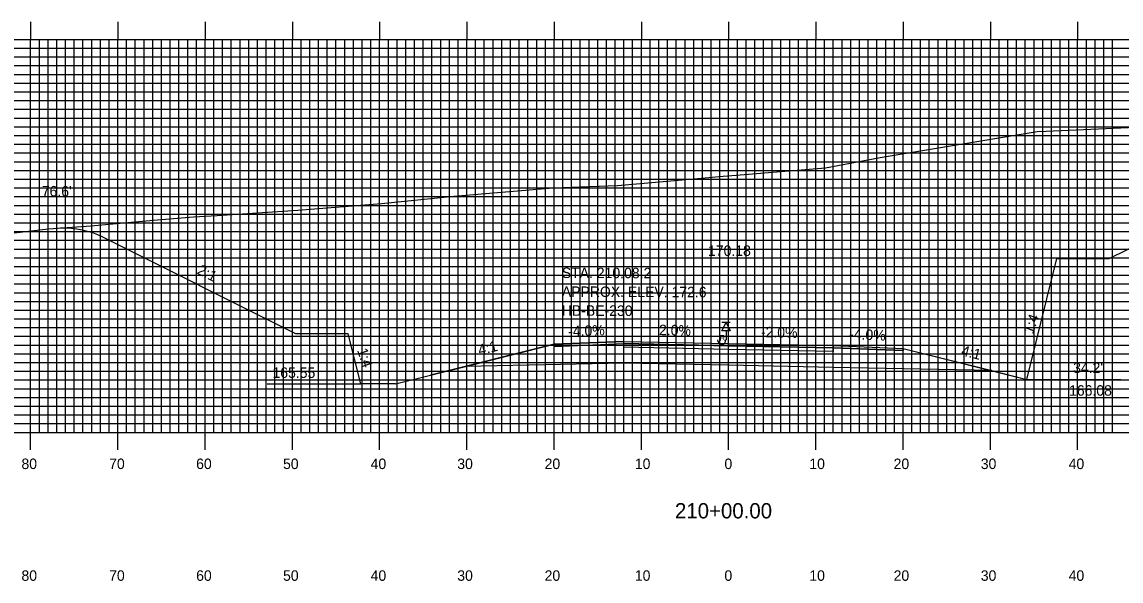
# Model space of a CAD drawing. Extents: x 1794453 to 1794796, y 442591 to 442811.
# Drawn here: x 1794537.4 to 1794663.3, y 442656.6 to 442720.7 of the extents above; entities that cross this region are included whole.
import ezdxf

# ---------------------------------------------------------------- set-up
doc = ezdxf.new("R2010")
doc.units = 0
for name, color, linetype in [('ANNOTATION', 7, 'Continuous'), ('BORING - REFUSAL', 7, 'Continuous'), ('D_Roadway_Centerline', 7, 'Continuous'), ('D_Roadway_Centerline_Text', 7, 'Continuous'), ('D_Roadway_Edge_Shoulder', 7, 'Continuous'), ('D_Roadway_Edge_TW', 7, 'Continuous'), ('D_Roadway_FinishedGrade', 7, 'Continuous'), ('D_Roadway_Pavement', 7, 'Continuous'), ('D_Roadway_SlopeLines', 7, 'Continuous'), ('D_Roadway_SubGrade', 7, 'Continuous'), ('D_Text_Standard', 7, 'Continuous'), ('H_V ANNOTATION', 7, 'Continuous'), ('MAJOR', 7, 'Continuous'), ('MINOR', 7, 'Continuous'), ('PDRAIN', 7, 'Continuous'), ('S_Roadway_Centerline', 7, 'Continuous')]:
    doc.layers.add(name, color=color, linetype=linetype)

msp = doc.modelspace()

# ---------------------------------------------------------------- linework, layer by layer
at = {"layer": 'BORING - REFUSAL'}
for p, q in [((1794618.52, 442686.27), (1794617.56, 442686.27)), ((1794618.04, 442685.31), (1794618.04, 442684.25))]:
    msp.add_line(p, q, dxfattribs=at)
msp.add_lwpolyline([(1794618.04, 442686.27), (1794618.52, 442685.31), (1794617.56, 442685.31)], close=True, dxfattribs=at)
msp.add_arc((1794617.55, 442684.25), 0.485, 180, 0, dxfattribs=at)
at = {"layer": 'D_Roadway_Centerline'}
msp.add_lwpolyline([(1794580.17, 442679.22), (1794588.17, 442681.22), (1794598.34, 442683.77), (1794606.34, 442684.09), (1794618.34, 442683.85), (1794630.34, 442683.61), (1794638.34, 442683.29), (1794648.51, 442680.74), (1794652.51, 442679.74)], dxfattribs=at)
at = {"layer": 'D_Roadway_Edge_Shoulder'}
for points in [[(1794606.34, 442684.09), (1794598.34, 442683.77), (1794598.34, 442683.52), (1794606.34, 442683.84)], [(1794630.34, 442683.61), (1794638.34, 442683.29), (1794638.34, 442683.04), (1794630.34, 442683.36)]]:
    msp.add_lwpolyline(points, close=True, dxfattribs=at)
at = {"layer": 'D_Roadway_Edge_TW'}
msp.add_lwpolyline([(1794606.34, 442683.84), (1794606.34, 442684.09), (1794618.34, 442683.85), (1794630.34, 442683.61), (1794630.34, 442683.36), (1794618.34, 442683.6)], close=True, dxfattribs=at)
at = {"layer": 'D_Roadway_FinishedGrade'}
msp.add_arc((1794542.15, 442687.07), 10, 63.4349, 92.1761, dxfattribs=at)
at = {"layer": 'D_Roadway_Pavement'}
msp.add_lwpolyline([(1794606.34, 442683.42), (1794606.34, 442683.84), (1794618.34, 442683.6), (1794630.34, 442683.36), (1794630.34, 442682.94), (1794618.34, 442683.18)], close=True, dxfattribs=at)
at = {"layer": 'D_Roadway_SlopeLines'}
for p, q in [((1794661.97, 442693.57), (1794686.33, 442705.74)), ((1794652.51, 442679.74), (1794655.97, 442693.57)), ((1794655.97, 442693.57), (1794661.97, 442693.57)), ((1794580.17, 442679.22), (1794576.17, 442679.22))]:
    msp.add_line(p, q, dxfattribs=at)
for points in [[(1794574.73, 442684.97), (1794568.73, 442684.97), (1794546.62, 442696.02)], [(1794576.17, 442679.22), (1794574.73, 442684.97), (1794568.73, 442684.97)], [(1794598.34, 442683.77), (1794584.17, 442680.22)], [(1794638.34, 442683.29), (1794652.51, 442679.74)]]:
    msp.add_lwpolyline(points, dxfattribs=at)
at = {"layer": 'D_Roadway_SubGrade'}
msp.add_lwpolyline([(1794606.34, 442681.59), (1794588.17, 442681.22), (1794598.34, 442683.77), (1794598.34, 442683.52), (1794606.34, 442683.84), (1794618.34, 442683.6), (1794630.34, 442683.36), (1794638.34, 442683.04), (1794638.34, 442683.29), (1794648.51, 442680.74), (1794630.34, 442681.11), (1794618.34, 442681.35)], close=True, dxfattribs=at)
at = {"layer": 'MAJOR'}
for p, q in [((1794538.34, 442720.67), (1794538.34, 442718.67)), ((1794548.34, 442720.67), (1794548.34, 442718.67)), ((1794558.34, 442720.67), (1794558.34, 442718.67)), ((1794568.34, 442720.67), (1794568.34, 442718.67)), ((1794578.34, 442720.67), (1794578.34, 442718.67)), ((1794588.34, 442720.67), (1794588.34, 442718.67)), ((1794598.34, 442720.67), (1794598.34, 442718.67)), ((1794608.34, 442720.67), (1794608.34, 442718.67)), ((1794618.34, 442720.67), (1794618.34, 442718.67)), ((1794628.34, 442720.67), (1794628.34, 442718.67)), ((1794638.34, 442720.67), (1794638.34, 442718.67)), ((1794648.34, 442720.67), (1794648.34, 442718.67)), ((1794658.34, 442720.67), (1794658.34, 442718.67)), ((1794478.34, 442718.67), (1794758.34, 442718.67)), ((1794478.34, 442718.67), (1794758.34, 442718.67)), ((1794538.34, 442673.67), (1794538.34, 442718.67)), ((1794548.34, 442673.67), (1794548.34, 442718.67)), ((1794558.34, 442673.67), (1794558.34, 442718.67)), ((1794568.34, 442673.67), (1794568.34, 442718.67)), ((1794578.34, 442673.67), (1794578.34, 442718.67)), ((1794588.34, 442673.67), (1794588.34, 442718.67)), ((1794598.34, 442673.67), (1794598.34, 442718.67)), ((1794608.34, 442673.67), (1794608.34, 442718.67)), ((1794618.34, 442673.67), (1794618.34, 442718.67)), ((1794628.34, 442673.67), (1794628.34, 442718.67)), ((1794638.34, 442673.67), (1794638.34, 442718.67)), ((1794648.34, 442673.67), (1794648.34, 442718.67)), ((1794658.34, 442673.67), (1794658.34, 442718.67)), ((1794478.34, 442713.67), (1794758.34, 442713.67)), ((1794478.34, 442708.67), (1794758.34, 442708.67)), ((1794478.34, 442703.67), (1794758.34, 442703.67)), ((1794478.34, 442698.67), (1794758.34, 442698.67)), ((1794478.34, 442693.67), (1794758.34, 442693.67)), ((1794478.34, 442688.67), (1794758.34, 442688.67)), ((1794478.34, 442683.67), (1794758.34, 442683.67)), ((1794478.34, 442678.67), (1794758.34, 442678.67)), ((1794478.34, 442673.67), (1794758.34, 442673.67)), ((1794478.34, 442673.67), (1794758.34, 442673.67)), ((1794538.34, 442671.66), (1794538.34, 442673.67)), ((1794548.34, 442671.66), (1794548.34, 442673.67)), ((1794558.34, 442671.66), (1794558.34, 442673.67)), ((1794568.34, 442671.66), (1794568.34, 442673.67)), ((1794578.34, 442671.66), (1794578.34, 442673.67)), ((1794588.34, 442671.66), (1794588.34, 442673.67)), ((1794598.34, 442671.66), (1794598.34, 442673.67)), ((1794608.34, 442671.66), (1794608.34, 442673.67)), ((1794618.34, 442671.66), (1794618.34, 442673.67)), ((1794628.34, 442671.66), (1794628.34, 442673.67)), ((1794638.34, 442671.66), (1794638.34, 442673.67)), ((1794648.34, 442671.66), (1794648.34, 442673.67)), ((1794658.34, 442671.66), (1794658.34, 442673.67))]:
    msp.add_line(p, q, dxfattribs=at)
at = {"layer": 'MINOR'}
for p, q in [((1794539.34, 442673.67), (1794539.34, 442718.67)), ((1794540.34, 442673.67), (1794540.34, 442718.67)), ((1794541.34, 442673.67), (1794541.34, 442718.67)), ((1794542.34, 442673.67), (1794542.34, 442718.67)), ((1794543.34, 442673.67), (1794543.34, 442718.67)), ((1794544.34, 442673.67), (1794544.34, 442718.67)), ((1794545.34, 442673.67), (1794545.34, 442718.67)), ((1794546.34, 442673.67), (1794546.34, 442718.67)), ((1794547.34, 442673.67), (1794547.34, 442718.67)), ((1794549.34, 442673.67), (1794549.34, 442718.67)), ((1794550.34, 442673.67), (1794550.34, 442718.67)), ((1794551.34, 442673.67), (1794551.34, 442718.67)), ((1794552.34, 442673.67), (1794552.34, 442718.67)), ((1794553.34, 442673.67), (1794553.34, 442718.67)), ((1794554.34, 442673.67), (1794554.34, 442718.67)), ((1794555.34, 442673.67), (1794555.34, 442718.67)), ((1794556.34, 442673.67), (1794556.34, 442718.67)), ((1794557.34, 442673.67), (1794557.34, 442718.67)), ((1794559.34, 442673.67), (1794559.34, 442718.67)), ((1794560.34, 442673.67), (1794560.34, 442718.67)), ((1794561.34, 442673.67), (1794561.34, 442718.67)), ((1794562.34, 442673.67), (1794562.34, 442718.67)), ((1794563.34, 442673.67), (1794563.34, 442718.67)), ((1794564.34, 442673.67), (1794564.34, 442718.67)), ((1794565.34, 442673.67), (1794565.34, 442718.67)), ((1794566.34, 442673.67), (1794566.34, 442718.67)), ((1794567.34, 442673.67), (1794567.34, 442718.67)), ((1794569.34, 442673.67), (1794569.34, 442718.67)), ((1794570.34, 442673.67), (1794570.34, 442718.67)), ((1794571.34, 442673.67), (1794571.34, 442718.67)), ((1794572.34, 442673.67), (1794572.34, 442718.67)), ((1794573.34, 442673.67), (1794573.34, 442718.67)), ((1794574.34, 442673.67), (1794574.34, 442718.67)), ((1794575.34, 442673.67), (1794575.34, 442718.67)), ((1794576.34, 442673.67), (1794576.34, 442718.67)), ((1794577.34, 442673.67), (1794577.34, 442718.67)), ((1794579.34, 442673.67), (1794579.34, 442718.67)), ((1794580.34, 442673.67), (1794580.34, 442718.67)), ((1794581.34, 442673.67), (1794581.34, 442718.67)), ((1794582.34, 442673.67), (1794582.34, 442718.67)), ((1794583.34, 442673.67), (1794583.34, 442718.67)), ((1794584.34, 442673.67), (1794584.34, 442718.67)), ((1794585.34, 442673.67), (1794585.34, 442718.67)), ((1794586.34, 442673.67), (1794586.34, 442718.67)), ((1794587.34, 442673.67), (1794587.34, 442718.67)), ((1794589.34, 442673.67), (1794589.34, 442718.67)), ((1794590.34, 442673.67), (1794590.34, 442718.67)), ((1794591.34, 442673.67), (1794591.34, 442718.67)), ((1794592.34, 442673.67), (1794592.34, 442718.67)), ((1794593.34, 442673.67), (1794593.34, 442718.67)), ((1794594.34, 442673.67), (1794594.34, 442718.67)), ((1794595.34, 442673.67), (1794595.34, 442718.67)), ((1794596.34, 442673.67), (1794596.34, 442718.67)), ((1794597.34, 442673.67), (1794597.34, 442718.67)), ((1794599.34, 442673.67), (1794599.34, 442718.67)), ((1794600.34, 442673.67), (1794600.34, 442718.67)), ((1794601.34, 442673.67), (1794601.34, 442718.67)), ((1794602.34, 442673.67), (1794602.34, 442718.67)), ((1794603.34, 442673.67), (1794603.34, 442718.67)), ((1794604.34, 442673.67), (1794604.34, 442718.67)), ((1794605.34, 442673.67), (1794605.34, 442718.67)), ((1794606.34, 442673.67), (1794606.34, 442718.67)), ((1794607.34, 442673.67), (1794607.34, 442718.67)), ((1794609.34, 442673.67), (1794609.34, 442718.67)), ((1794610.34, 442673.67), (1794610.34, 442718.67)), ((1794611.34, 442673.67), (1794611.34, 442718.67)), ((1794612.34, 442673.67), (1794612.34, 442718.67)), ((1794613.34, 442673.67), (1794613.34, 442718.67)), ((1794614.34, 442673.67), (1794614.34, 442718.67)), ((1794615.34, 442673.67), (1794615.34, 442718.67)), ((1794616.34, 442673.67), (1794616.34, 442718.67)), ((1794617.34, 442673.67), (1794617.34, 442718.67)), ((1794619.34, 442673.67), (1794619.34, 442718.67)), ((1794620.34, 442673.67), (1794620.34, 442718.67)), ((1794621.34, 442673.67), (1794621.34, 442718.67)), ((1794622.34, 442673.67), (1794622.34, 442718.67)), ((1794623.34, 442673.67), (1794623.34, 442718.67)), ((1794624.34, 442673.67), (1794624.34, 442718.67)), ((1794625.34, 442673.67), (1794625.34, 442718.67)), ((1794626.34, 442673.67), (1794626.34, 442718.67)), ((1794627.34, 442673.67), (1794627.34, 442718.67)), ((1794629.34, 442673.67), (1794629.34, 442718.67)), ((1794630.34, 442673.67), (1794630.34, 442718.67)), ((1794631.34, 442673.67), (1794631.34, 442718.67)), ((1794632.34, 442673.67), (1794632.34, 442718.67)), ((1794633.34, 442673.67), (1794633.34, 442718.67)), ((1794634.34, 442673.67), (1794634.34, 442718.67)), ((1794635.34, 442673.67), (1794635.34, 442718.67)), ((1794636.34, 442673.67), (1794636.34, 442718.67)), ((1794637.34, 442673.67), (1794637.34, 442718.67)), ((1794639.34, 442673.67), (1794639.34, 442718.67)), ((1794640.34, 442673.67), (1794640.34, 442718.67)), ((1794641.34, 442673.67), (1794641.34, 442718.67)), ((1794642.34, 442673.67), (1794642.34, 442718.67)), ((1794643.34, 442673.67), (1794643.34, 442718.67)), ((1794644.34, 442673.67), (1794644.34, 442718.67)), ((1794645.34, 442673.67), (1794645.34, 442718.67)), ((1794646.34, 442673.67), (1794646.34, 442718.67)), ((1794647.34, 442673.67), (1794647.34, 442718.67)), ((1794649.34, 442673.67), (1794649.34, 442718.67)), ((1794650.34, 442673.67), (1794650.34, 442718.67)), ((1794651.34, 442673.67), (1794651.34, 442718.67)), ((1794652.34, 442673.67), (1794652.34, 442718.67)), ((1794653.34, 442673.67), (1794653.34, 442718.67)), ((1794654.34, 442673.67), (1794654.34, 442718.67)), ((1794655.34, 442673.67), (1794655.34, 442718.67)), ((1794656.34, 442673.67), (1794656.34, 442718.67)), ((1794657.34, 442673.67), (1794657.34, 442718.67)), ((1794659.34, 442673.67), (1794659.34, 442718.67)), ((1794660.34, 442673.67), (1794660.34, 442718.67)), ((1794661.34, 442673.67), (1794661.34, 442718.67)), ((1794662.34, 442673.67), (1794662.34, 442718.67)), ((1794478.34, 442717.67), (1794758.34, 442717.67)), ((1794478.34, 442716.67), (1794758.34, 442716.67)), ((1794478.34, 442715.67), (1794758.34, 442715.67)), ((1794478.34, 442714.67), (1794758.34, 442714.67)), ((1794478.34, 442712.67), (1794758.34, 442712.67)), ((1794478.34, 442711.67), (1794758.34, 442711.67)), ((1794478.34, 442710.67), (1794758.34, 442710.67)), ((1794478.34, 442709.67), (1794758.34, 442709.67)), ((1794478.34, 442707.67), (1794758.34, 442707.67)), ((1794478.34, 442706.67), (1794758.34, 442706.67)), ((1794478.34, 442705.67), (1794758.34, 442705.67)), ((1794478.34, 442704.67), (1794758.34, 442704.67)), ((1794478.34, 442702.67), (1794758.34, 442702.67)), ((1794478.34, 442701.67), (1794758.34, 442701.67)), ((1794478.34, 442700.67), (1794758.34, 442700.67)), ((1794478.34, 442699.67), (1794758.34, 442699.67)), ((1794478.34, 442697.67), (1794758.34, 442697.67)), ((1794478.34, 442696.67), (1794758.34, 442696.67)), ((1794478.34, 442695.67), (1794758.34, 442695.67)), ((1794478.34, 442694.67), (1794758.34, 442694.67)), ((1794478.34, 442692.67), (1794758.34, 442692.67)), ((1794478.34, 442691.67), (1794758.34, 442691.67)), ((1794478.34, 442690.67), (1794758.34, 442690.67)), ((1794478.34, 442689.67), (1794758.34, 442689.67)), ((1794478.34, 442687.67), (1794758.34, 442687.67)), ((1794478.34, 442686.67), (1794758.34, 442686.67)), ((1794478.34, 442685.67), (1794758.34, 442685.67)), ((1794478.34, 442684.67), (1794758.34, 442684.67)), ((1794478.34, 442682.67), (1794758.34, 442682.67)), ((1794478.34, 442681.67), (1794758.34, 442681.67)), ((1794478.34, 442680.67), (1794758.34, 442680.67)), ((1794478.34, 442679.67), (1794758.34, 442679.67)), ((1794478.34, 442677.67), (1794758.34, 442677.67)), ((1794478.34, 442676.67), (1794758.34, 442676.67)), ((1794478.34, 442675.67), (1794758.34, 442675.67)), ((1794478.34, 442674.67), (1794758.34, 442674.67))]:
    msp.add_line(p, q, dxfattribs=at)
at = {"layer": 'PDRAIN'}
for p, q in [((1794565.44, 442679.22), (1794576.17, 442679.22)), ((1794652.51, 442679.74), (1794663.28, 442679.74))]:
    msp.add_line(p, q, dxfattribs=at)
at = {"layer": 'S_Roadway_Centerline'}
msp.add_lwpolyline([(1794523.03, 442694.94), (1794540.4, 442696.97), (1794545.25, 442697.32), (1794552.41, 442697.96), (1794556.99, 442698.37), (1794559.72, 442698.52), (1794568.96, 442699.11), (1794578.56, 442699.88), (1794586.84, 442700.73), (1794598.23, 442701.68), (1794605.59, 442701.94), (1794616.07, 442702.85), (1794617.23, 442702.96), (1794619.19, 442703.13), (1794629.43, 442703.96), (1794635.69, 442705.14), (1794653.69, 442708.11), (1794654.74, 442708.17), (1794665.86, 442708.65)], dxfattribs=at)

# ---------------------------------------------------------------- texts
at = {"layer": 'ANNOTATION'}
for s, rotation, p in [('2:1', 333.4349, (1794557.33, 442691.88)), ('2:1', 333.4349, (1794557.33, 442691.88)), ('1:4', 70.516, (1794653.21, 442684.85)), ('1:4', 70.516, (1794653.21, 442684.85)), ('-4.0%', 2.2906, (1794599.97, 442684.63)), ('2.0%', 358.8542, (1794610.35, 442684.81)), ('-2.0%', 358.8542, (1794622.03, 442684.57)), ('-4.0%', 357.7094, (1794632.13, 442684.34)), ('1:4', 289.484, (1794575.74, 442683.08)), ('1:4', 289.484, (1794575.74, 442683.08)), ('4:1', 14.0362, (1794589.79, 442682.49)), ('4:1', 345.9638, (1794644.93, 442682.5))]:
    msp.add_text(s, height=1.2, rotation=rotation, dxfattribs=at).set_placement(p)
for s, p in [("34.2'", (1794657.82, 442680.47)), ('165.55', (1794566.06, 442679.91)), ('166.08', (1794657.36, 442677.87))]:
    msp.add_text(s, height=1.2, dxfattribs=at).set_placement(p)
at = {"layer": 'BORING - REFUSAL'}
for s, p in [('STA. 210.08.2', (1794599.22, 442691.35)), ('APPROX. ELEV. 172.6', (1794599.22, 442689.19)), ('HB-BE-230', (1794599.21, 442687.03))]:
    msp.add_text(s, height=1.2, rotation=359.8142, dxfattribs=at).set_placement(p)
msp.add_text('R', height=0.64, dxfattribs=at).set_placement((1794617.33, 442684.19))
at = {"layer": 'D_Roadway_Centerline'}
for s, p in [('C', (1794618.33, 442683.85)), ('L', (1794618.34, 442683.84))]:
    msp.add_text(s, height=0.0146, dxfattribs=at).set_placement(p)
at = {"layer": 'D_Roadway_Centerline_Text'}
msp.add_text('170.18', height=1.2, dxfattribs=at).set_placement((1794615.98, 442693.88))
at = {"layer": 'D_Text_Standard'}
msp.add_text("76.6'", height=1.2, dxfattribs=at).set_placement((1794539.62, 442700.69))
at = {"layer": 'H_V ANNOTATION'}
for s, height, p in [('80', 1.2, (1794537.29, 442669.47)), ('70', 1.2, (1794547.34, 442669.47)), ('60', 1.2, (1794557.31, 442669.47)), ('50', 1.2, (1794567.27, 442669.47)), ('40', 1.2, (1794577.31, 442669.47)), ('30', 1.2, (1794587.24, 442669.47)), ('20', 1.2, (1794597.25, 442669.47)), ('10', 1.2, (1794607.59, 442669.47)), ('0', 1.2, (1794617.86, 442669.47)), ('10', 1.2, (1794627.59, 442669.47)), ('20', 1.2, (1794637.25, 442669.47)), ('30', 1.2, (1794647.24, 442669.47)), ('40', 1.2, (1794657.31, 442669.47)), ('210+00.00', 1.75, (1794612.19, 442663.82)), ('80', 1.2, (1794537.29, 442656.67)), ('70', 1.2, (1794547.34, 442656.67)), ('60', 1.2, (1794557.31, 442656.67)), ('50', 1.2, (1794567.27, 442656.67)), ('40', 1.2, (1794577.31, 442656.67)), ('30', 1.2, (1794587.24, 442656.67)), ('20', 1.2, (1794597.25, 442656.67)), ('10', 1.2, (1794607.59, 442656.67)), ('0', 1.2, (1794617.86, 442656.67)), ('10', 1.2, (1794627.59, 442656.67)), ('20', 1.2, (1794637.25, 442656.67)), ('30', 1.2, (1794647.24, 442656.67)), ('40', 1.2, (1794657.31, 442656.67))]:
    msp.add_text(s, height=height, dxfattribs=at).set_placement(p)

doc.saveas('drawing.dxf')
